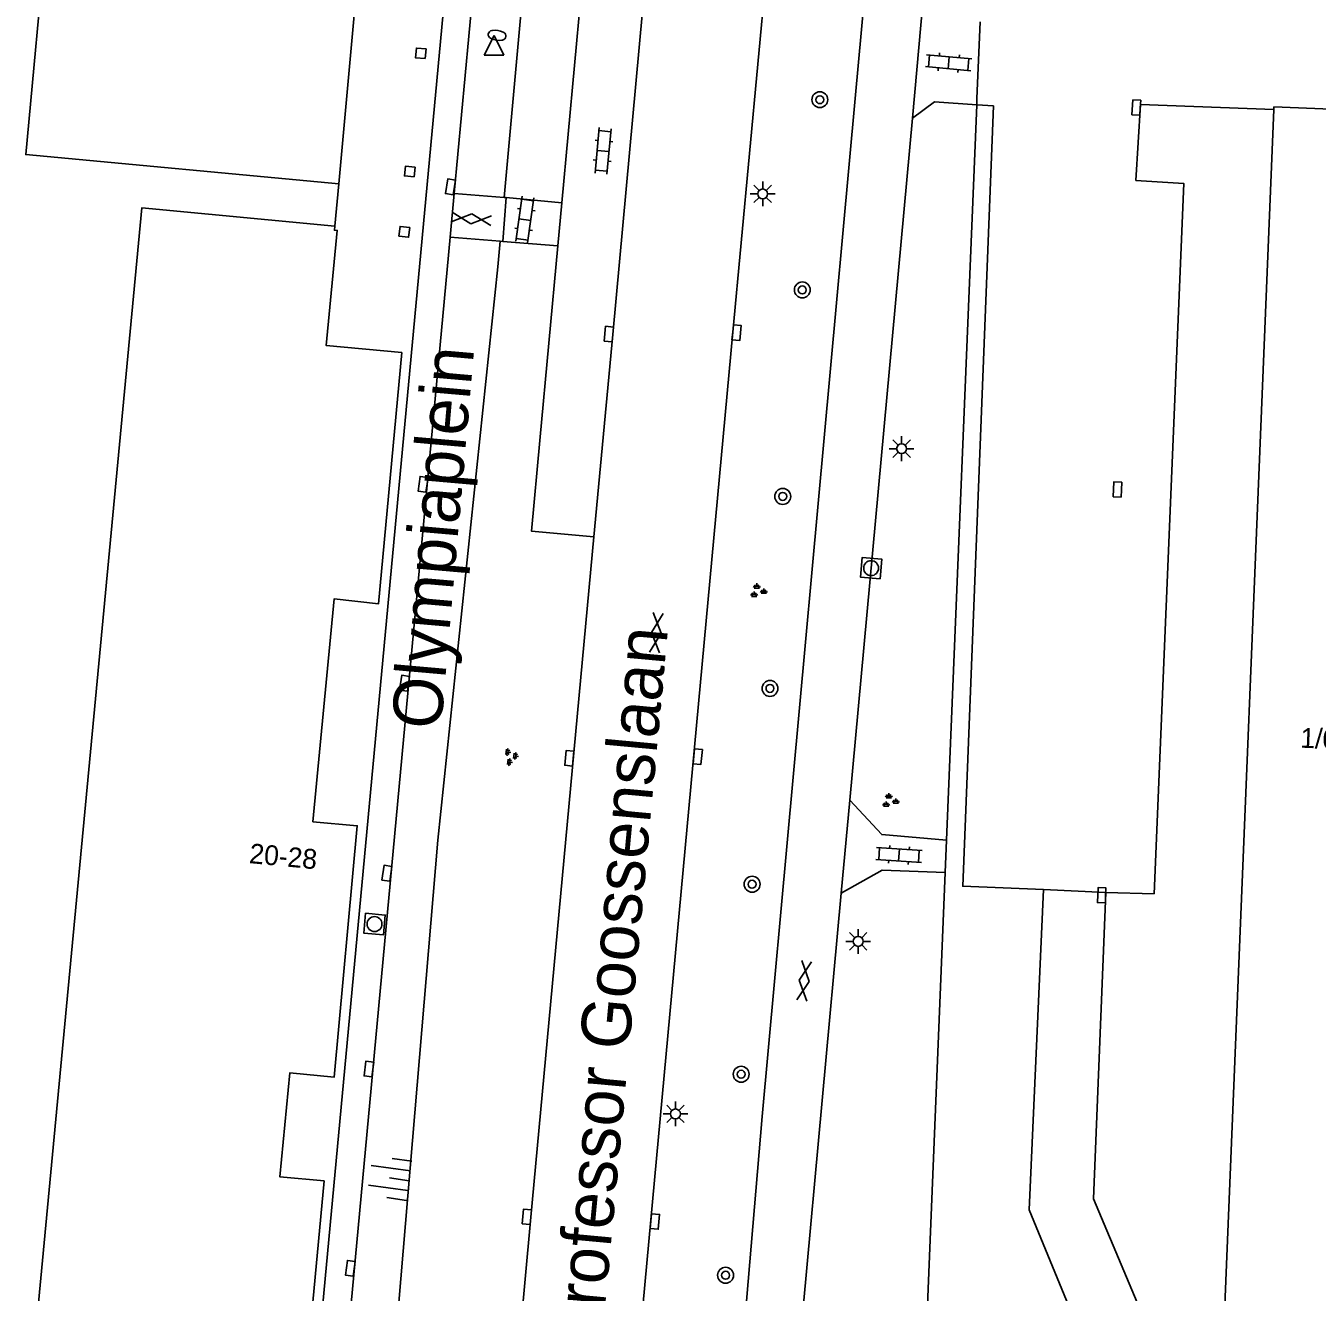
# Model space of a CAD drawing. Extents: x 132994 to 136000, y 393499 to 395512.
# Drawn here: x 133420.1 to 133485.2, y 394439.8 to 394503.7 of the extents above; entities that cross this region are included whole.
import ezdxf

# ---------------------------------------------------------------- set-up
doc = ezdxf.new("R2010")
doc.units = 0
for name, color, linetype in [('gg-afsc-hekwerk', 7, 'Continuous'), ('gg-afsc-muur', 7, 'Continuous'), ('gg-anno-huisnummerreeks BGT', 7, 'Continuous'), ('gg-anno-openbare ruimte label', 7, 'Continuous'), ('gg-bbg-hoofdgebouw', 7, 'Continuous'), ('gg-bbg-pand onderbouw', 7, 'Continuous'), ('gg-knt-BGT kruinlijn', 7, 'Continuous'), ('gg-knt-trap', 7, 'Continuous'), ('gg-knt-verharding', 7, 'Continuous'), ('gt-grn-vlakafsluiter', 7, 'Continuous'), ('gt-symb-boom', 7, 'Continuous'), ('gt-symb-brandkraan', 7, 'Continuous'), ('gt-symb-gesloten verharding', 7, 'Continuous'), ('gt-symb-groenvak', 7, 'Continuous'), ('gt-symb-klinker verharding', 7, 'Continuous'), ('gt-symb-kolk', 7, 'Continuous'), ('gt-symb-kolk center center', 7, 'Continuous'), ('gt-symb-lichtmast', 7, 'Continuous'), ('gt-symb-rioolschacht', 7, 'Continuous'), ('gt-symb-talud symbool', 7, 'Continuous'), ('gt-symb-waterafsluiter', 7, 'Continuous')]:
    doc.layers.add(name, color=color, linetype=linetype)

# ---------------------------------------------------------------- blocks, each defined once
blk = doc.blocks.new('gt0-KOLK')
at = {"layer": 'gt-symb-kolk'}
blk.add_lwpolyline([(0, 0), (0.375, 0), (0.375, 0.4), (-0.375, 0.4), (-0.375, 0), (0, 0)], dxfattribs=at)
blk = doc.blocks.new('gt0-KL1')
at = {"layer": 'gt-symb-klinker verharding'}
for p, q in [((-1.15, 0.3), (1.15, 0.3)), ((-1, -0.3), (-1, 0.3)), ((-0.5, 0.3), (-0.5, 0.45)), ((0, -0.3), (0, 0.3)), ((0.5, 0.3), (0.5, 0.45)), ((1, -0.3), (1, 0.3)), ((-1.15, -0.3), (1.15, -0.3)), ((-0.5, -0.45), (-0.5, -0.3)), ((0.5, -0.45), (0.5, -0.3))]:
    blk.add_line(p, q, dxfattribs=at)
blk = doc.blocks.new('gt0-GESVH1')
at = {"layer": 'gt-symb-gesloten verharding'}
for p, q in [((-0.992, -0.261), (0.008, 0.239)), ((0.008, -0.261), (-0.992, 0.239)), ((0.008, 0.239), (1.008, -0.261)), ((1.008, 0.239), (0.008, -0.261))]:
    blk.add_line(p, q, dxfattribs=at)
blk = doc.blocks.new('gt0-LMAST')
at = {"layer": 'gt-symb-lichtmast'}
for p, q in [((-0.182, 0.173), (-0.447, 0.438)), ((-0.005, 0.246), (-0.005, 0.621)), ((0.172, 0.173), (0.437, 0.438)), ((-0.255, -0.004), (-0.63, -0.004)), ((-0.182, -0.181), (-0.447, -0.446)), ((-0.005, -0.254), (-0.005, -0.629)), ((0.437, -0.446), (0.172, -0.181)), ((0.245, -0.004), (0.62, -0.004))]:
    blk.add_line(p, q, dxfattribs=at)
blk.add_circle((-0.005, -0.004), 0.25, dxfattribs=at)
blk = doc.blocks.new('gt0-GRVAK')
at = {"layer": 'gt-symb-groenvak'}
for p, q in [((-0.11, 0.189), (-0.228, 0.24)), ((-0.182, 0.153), (0.088, 0.153)), ((-0.091, 0.211), (-0.156, 0.322)), ((-0.047, 0.214), (-0.047, 0.393)), ((-0.004, 0.211), (0.061, 0.322)), ((0.015, 0.189), (0.133, 0.24)), ((0.262, -0.052), (0.197, 0.059)), ((0.305, -0.049), (0.305, 0.13)), ((0.349, -0.052), (0.414, 0.059)), ((-0.245, -0.228), (-0.363, -0.177)), ((-0.318, -0.264), (-0.047, -0.264)), ((-0.226, -0.206), (-0.291, -0.095)), ((-0.183, -0.203), (-0.183, -0.024)), ((-0.139, -0.206), (-0.074, -0.095)), ((-0.12, -0.228), (-0.002, -0.177)), ((0.243, -0.074), (0.125, -0.023)), ((0.17, -0.11), (0.441, -0.11)), ((0.368, -0.074), (0.486, -0.023))]:
    blk.add_line(p, q, dxfattribs=at)
blk = doc.blocks.new('gt0-RS')
at = {"layer": 'gt-symb-rioolschacht'}
blk.add_lwpolyline([(-0.5, -0.5), (0.5, -0.5), (0.5, 0.5), (-0.5, 0.5)], close=True, dxfattribs=at)
blk.add_circle((0, 0), 0.375, dxfattribs=at)
blk = doc.blocks.new('gt0-BOOM')
at = {"layer": 'gt-symb-boom'}
for radius in [0.4, 0.2]:
    blk.add_circle((0, 0), radius, dxfattribs=at)
blk = doc.blocks.new('gt0-KOLKCC')
at = {"layer": 'gt-symb-kolk center center'}
blk.add_lwpolyline([(-0.375, 0.2), (0.375, 0.2), (0.375, -0.2), (-0.375, -0.2)], close=True, dxfattribs=at)
blk = doc.blocks.new('gt0-WAFSL')
at = {"layer": 'gt-symb-waterafsluiter'}
for p, q in [((-0.5, -0.333), (0, 0.667)), ((0, 0.667), (0.5, -0.333)), ((0.5, -0.333), (-0.5, -0.333))]:
    blk.add_line(p, q, dxfattribs=at)
blk = doc.blocks.new('gt0-BR')
at = {"layer": 'gt-symb-brandkraan'}
for centre, radius, start, end in [((-0.244, 0), 0.206, 107.56694, 252.43307), ((0.599, -2.664), 3, 106.89205, 107.56694), ((0, -0.691), 0.938, 73.10799, 106.89205), ((-0.599, -2.664), 3, 72.43309, 73.10799), ((0.244, 0), 0.206, 287.56695, 72.43309), ((0.599, 2.664), 3, 252.43307, 253.10797), ((0, 0.691), 0.938, 253.10797, 286.89206), ((-0.599, 2.664), 3, 286.89206, 287.56695)]:
    blk.add_arc(centre, radius, start, end, dxfattribs=at)
blk = doc.blocks.new('gt0-TALUD_1')
at = {"layer": 'gt-symb-talud symbool'}
for p, q in [((-1, -1), (-1, 0)), ((-0.5, -2), (-0.5, 0)), ((0, -1), (0, 0)), ((0.5, -2), (0.5, 0)), ((1, -1), (1, 0))]:
    blk.add_line(p, q, dxfattribs=at)

msp = doc.modelspace()

# ---------------------------------------------------------------- linework, layer by layer
at = {"layer": 'gg-afsc-hekwerk'}
for p, q in [((133468.197, 394503.867), (133468.039, 394500)), ((133468.026, 394499.69), (133466.506, 394462.579)), ((133468.039, 394500), (133468.026, 394499.69)), ((133466.506, 394462.579), (133466.44, 394460.958)), ((133466.44, 394460.958), (133465.1, 394428.256))]:
    msp.add_line(p, q, dxfattribs=at)
at = {"layer": 'gg-afsc-muur'}
for p, q in [((133441.671, 394495.213), (133445.812, 394539.605)), ((133435.729, 394431.123), (133441.471, 394492.999))]:
    msp.add_line(p, q, dxfattribs=at)
for points in [[(133431.067, 394542.274), (133424.296, 394542.932), (133420.061, 394497.175), (133435.843, 394495.703)], [(133433.921, 394432.615), (133420.196, 394433.897), (133425.906, 394494.478), (133435.643, 394493.568)]]:
    msp.add_lwpolyline(points, dxfattribs=at)
at = {"layer": 'gg-bbg-hoofdgebouw'}
msp.add_line((133480.42, 394436.29), (133483.015, 394499.445), dxfattribs=at)
for points in [[(133429.645, 394381.275), (133444.572, 394541.504), (133431.116, 394542.772)], [(133483.015, 394499.445), (133483.02, 394499.58), (133510.24, 394498.47), (133510.302, 394500), (133510.35, 394501.21), (133510.76, 394501.2), (133510.78, 394501.61), (133512.83, 394501.52), (133512.96, 394504.64), (133483.27, 394505.85)]]:
    msp.add_lwpolyline(points, dxfattribs=at)
at = {"layer": 'gg-bbg-pand onderbouw'}
msp.add_line((133435.843, 394495.703), (133435.643, 394493.568), dxfattribs=at)
for points in [[(133431.067, 394542.274), (133440.179, 394541.389), (133437.053, 394507.907), (133436.953, 394507.917), (133435.843, 394495.703)], [(133440.204, 394502.016), (133439.717, 394502.061), (133439.763, 394502.549), (133440.249, 394502.503), (133440.204, 394502.016)], [(133439.645, 394496.05), (133439.157, 394496.099), (133439.207, 394496.587), (133439.694, 394496.537), (133439.645, 394496.05)], [(133435.643, 394493.568), (133435.624, 394493.359), (133435.773, 394493.344), (133435.217, 394487.536), (133439.021, 394487.186), (133437.858, 394474.511), (133435.617, 394474.761), (133434.541, 394463.515), (133436.782, 394463.308), (133435.61, 394450.621), (133433.383, 394450.845), (133432.869, 394445.599), (133435.109, 394445.39), (133433.921, 394432.615)], [(133438.883, 394493.058), (133439.371, 394493.004), (133439.425, 394493.492), (133438.937, 394493.545), (133438.883, 394493.058)]]:
    msp.add_lwpolyline(points, dxfattribs=at)
at = {"layer": 'gg-knt-BGT kruinlijn'}
for points in [[(133444.186, 394495.014), (133447.025, 394526.273), (133448.312, 394539.323)], [(133438.166, 394430.886), (133440.847, 394462.581), (133443.867, 394491.504), (133443.985, 394492.805)]]:
    msp.add_lwpolyline(points, dxfattribs=at)
at = {"layer": 'gg-knt-trap'}
for p, q in [((133441.671, 394495.213), (133441.471, 394492.999)), ((133444.186, 394495.014), (133441.671, 394495.213)), ((133444.124, 394492.794), (133444.294, 394495.005)), ((133444.294, 394495.005), (133444.186, 394495.014)), ((133441.471, 394492.999), (133443.985, 394492.805)), ((133443.985, 394492.805), (133444.124, 394492.794))]:
    msp.add_line(p, q, dxfattribs=at)
at = {"layer": 'gg-knt-verharding'}
for p, q in [((133465.42, 394538.888), (133461.894, 394500)), ((133448.494, 394509.933), (133447.096, 394494.743)), ((133465.332, 394505.023), (133464.78, 394499.012)), ((133461.621, 394464.606), (133464.78, 394499.012)), ((133447.096, 394494.743), (133444.294, 394495.005)), ((133447.096, 394494.743), (133446.896, 394492.565)), ((133444.124, 394492.794), (133446.896, 394492.565)), ((133446.896, 394492.565), (133445.993, 394482.749)), ((133461.19, 394459.915), (133461.621, 394464.606))]:
    msp.add_line(p, q, dxfattribs=at)
for points in [[(133457.832, 394510.763), (133455.716, 394488.206), (133450.331, 394429.771)], [(133451.669, 394509.92), (133449.669, 394488.098), (133448.711, 394477.881)], [(133455.554, 394429.225), (133457.211, 394448.639), (133461.894, 394500)], [(133468.026, 394499.69), (133465.896, 394499.842), (133464.78, 394499.012)], [(133471.394, 394460.092), (133467.321, 394460.261), (133468.868, 394499.63), (133468.026, 394499.69)], [(133483.015, 394499.445), (133476.287, 394499.701), (133476.06, 394495.87), (133478.475, 394495.706), (133476.972, 394459.884), (133474.535, 394459.95)], [(133445.993, 394482.749), (133445.572, 394478.17), (133448.711, 394477.881)], [(133444.324, 394430.306), (133445.534, 394443.564), (133448.711, 394477.881)], [(133461.621, 394464.606), (133463.232, 394462.861), (133466.506, 394462.579)], [(133466.44, 394460.958), (133463.259, 394461.076), (133461.19, 394459.915)], [(133458.268, 394428.958), (133459.269, 394438.997), (133461.19, 394459.915)], [(133483.39, 394413.064), (133470.677, 394443.925), (133471.394, 394460.092)], [(133474.535, 394459.95), (133473.925, 394444.496), (133482.645, 394423.773)]]:
    msp.add_lwpolyline(points, dxfattribs=at)
at = {"layer": 'gt-grn-vlakafsluiter'}
msp.add_line((133471.394, 394460.092), (133474.535, 394459.95), dxfattribs=at)

# ---------------------------------------------------------------- block references
at = {"layer": 'gt-symb-boom'}
for p in [(133460.114, 394499.942), (133459.228, 394490.345), (133458.242, 394479.926), (133457.598, 394470.239), (133456.696, 394460.36), (133456.144, 394450.773), (133455.358, 394440.632)]:
    msp.add_blockref('gt0-BOOM', p, dxfattribs=at)
at = {"layer": 'gt-symb-brandkraan', "rotation": 171.31914941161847}
msp.add_blockref('gt0-BR', (133443.833, 394503.191), dxfattribs=at)
at = {"layer": 'gt-symb-gesloten verharding'}
for p, rotation in [((133442.529, 394493.944), -5.220361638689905), ((133451.853, 394473.039), 84.77963836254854), ((133459.314, 394455.481), 82.81812146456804)]:
    msp.add_blockref('gt0-GESVH1', p, dxfattribs=dict(at, rotation=rotation))
at = {"layer": 'gt-symb-groenvak'}
for p in [(133456.98, 394475.149), (133463.639, 394464.564)]:
    msp.add_blockref('gt0-GRVAK', p, dxfattribs=at)
at = {"layer": 'gt-symb-groenvak', "rotation": -97.99231392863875}
msp.add_blockref('gt0-GRVAK', (133444.524, 394466.82), dxfattribs=at)
at = {"layer": 'gt-symb-klinker verharding'}
for p, rotation in [((133466.612, 394501.805), -5.220361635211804), ((133449.176, 394497.359), 84.77963836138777), ((133445.234, 394493.894), -97.9355503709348), ((133464.106, 394461.835), -3.7835902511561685)]:
    msp.add_blockref('gt0-KL1', p, dxfattribs=dict(at, rotation=rotation))
at = {"layer": 'gt-symb-kolk'}
for p, rotation in [((133476.279, 394499.536), 86.6167123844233), ((133455.716, 394488.206), -95.22036163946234), ((133449.669, 394488.098), 84.77963836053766), ((133475.326, 394480.267), 87.59258615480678), ((133447.676, 394466.696), 84.72259391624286), ((133453.753, 394466.814), -95.2774060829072), ((133474.53, 394459.797), 87.76436310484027), ((133445.534, 394443.564), 84.77963836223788), ((133451.595, 394443.362), -95.2774060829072)]:
    msp.add_blockref('gt0-KOLK', p, dxfattribs=dict(at, rotation=rotation))
at = {"layer": 'gt-symb-kolk center center'}
for p, rotation in [((133441.484, 394495.542), -98.97262661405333), ((133440.097, 394480.538), -98.16250946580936), ((133439.167, 394470.501), -98.16250946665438), ((133438.273, 394460.916), -98.21920925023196), ((133437.367, 394451.037), -97.181878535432), ((133436.43, 394440.986), -97.81418085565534)]:
    msp.add_blockref('gt0-KOLKCC', p, dxfattribs=dict(at, rotation=rotation))
at = {"layer": 'gt-symb-lichtmast'}
for p in [(133457.235, 394495.193), (133464.241, 394482.338), (133462.054, 394457.48), (133452.836, 394448.777)]:
    msp.add_blockref('gt0-LMAST', p, dxfattribs=at)
at = {"layer": 'gt-symb-rioolschacht'}
for p, rotation in [((133462.7, 394476.307), 84.7225939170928), ((133437.649, 394458.35), -95.39146339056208)]:
    msp.add_blockref('gt0-RS', p, dxfattribs=dict(at, rotation=rotation))
at = {"layer": 'gt-symb-talud symbool', "xscale": 0.9997104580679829, "yscale": 0.999710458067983, "rotation": -97.9923139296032}
msp.add_blockref('gt0-TALUD_1', (133439.394, 394445.402), dxfattribs=at)
at = {"layer": 'gt-symb-waterafsluiter'}
msp.add_blockref('gt0-WAFSL', (133443.681, 394502.522), dxfattribs=at)

# ---------------------------------------------------------------- texts
at = {"layer": 'gg-anno-huisnummerreeks BGT'}
for s, rotation, p in [('1/01', 357.6, (133484.335, 394467.252)), ('20-28', 354.7, (133431.301, 394461.428))]:
    msp.add_text(s, height=1, rotation=rotation, dxfattribs=at).set_placement(p)
at = {"layer": 'gg-anno-openbare ruimte label'}
for s, rotation, p in [('Olympiaplein', 85, (133440.994, 394468.122)), ('Professor Goossenslaan', 84.7, (133449.073, 394436.774))]:
    msp.add_text(s, height=2.5, rotation=rotation, dxfattribs=at).set_placement(p)

doc.saveas('drawing.dxf')
